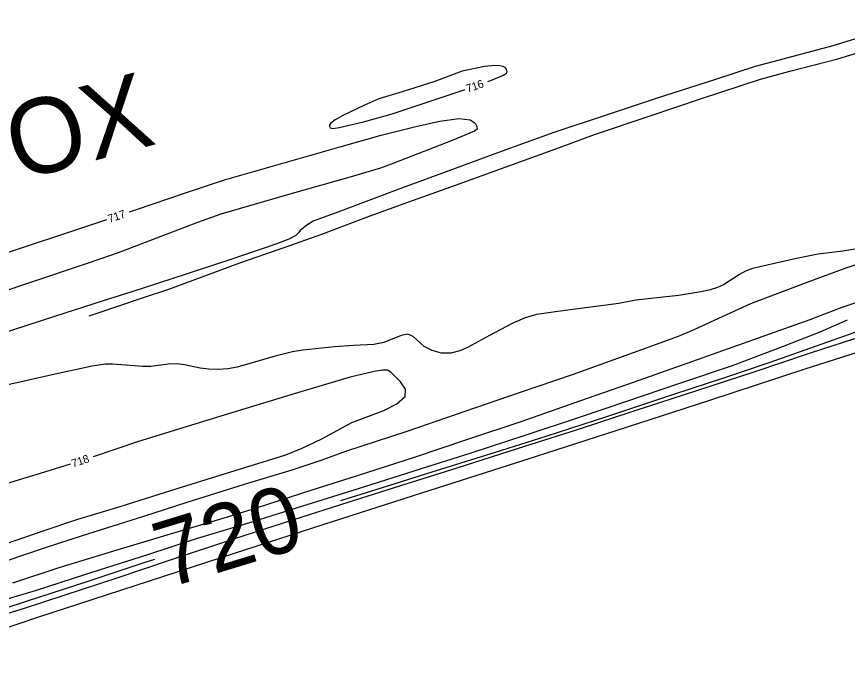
# Model space of a CAD drawing. Extents: x -361782338 to 28259792, y -263199453 to 8342113.
# Drawn here: x 1404244.3 to 1404659.4, y 576533.7 to 576861.6 of the extents above; entities that cross this region are included whole.
import ezdxf

# ---------------------------------------------------------------- set-up
doc = ezdxf.new("R2010")
doc.units = 0
for name, color, linetype in [('DT_X_Contour_Minor', 7, 'Continuous'), ('Level 14', 7, 'Continuous'), ('Level 19', 7, 'Continuous'), ('Level 40', 7, 'Continuous')]:
    doc.layers.add(name, color=color, linetype=linetype)

msp = doc.modelspace()

# ---------------------------------------------------------------- linework, layer by layer
at = {"layer": 'DT_X_Contour_Minor'}
for points in [[(1404699.46, 576861.58), (1404682.89, 576856.44), (1404652.1, 576846.96), (1404643.88, 576844.78)], [(1404280.47, 576711.95), (1404285.06, 576713.53), (1404307.26, 576720.99), (1404320.36, 576725.27), (1404337.02, 576731.47), (1404355.85, 576738.56), (1404378.05, 576746.14), (1404396.8, 576752.78), (1404421.02, 576762.02), (1404440.28, 576769.04), (1404463.56, 576777.37), (1404488.43, 576786.24), (1404515.51, 576796.09), (1404533.09, 576802.63), (1404560.28, 576811.8), (1404586.55, 576820.64), (1404616.02, 576830.31), (1404630.66, 576834.29), (1404654.64, 576840.5), (1404666.62, 576844.09)], [(1404643.88, 576844.78), (1404627.84, 576840.51), (1404613.37, 576836.57), (1404593.46, 576830.22), (1404563.83, 576820.63), (1404538.86, 576812.39), (1404512.65, 576803.66), (1404485.09, 576793.72), (1404460.32, 576784.56), (1404437.13, 576775.99), (1404404.79, 576763.83), (1404392.38, 576759.34), (1404389.33, 576757.38), (1404386.78, 576755.27)], [(1404479.73, 576829.1), (1404481.58, 576829.73), (1404487.62, 576832.33), (1404489.05, 576833.24), (1404489.47, 576833.93), (1404489.08, 576835.29), (1404488.52, 576836.02), (1404487.42, 576836.63), (1404485.63, 576837.02), (1404483.31, 576837.15), (1404478.11, 576836.65), (1404466.83, 576834.29), (1404452.71, 576828.93), (1404436.85, 576823.9), (1404425.34, 576820.48), (1404417.73, 576817.12), (1404407.66, 576812.26), (1404403.45, 576809.96), (1404401.22, 576808.34), (1404400.54, 576807.3), (1404400.63, 576806.56), (1404401, 576805.95), (1404402.29, 576805.71), (1404405.44, 576806.12), (1404417.58, 576809.05), (1404431.93, 576812.99), (1404457.98, 576821.63), (1404468.38, 576825.2)], [(1404300.71, 576763.93), (1404304.26, 576765.13), (1404328.6, 576773.47), (1404348.1, 576779.96), (1404372.67, 576786.91), (1404405.27, 576796.28), (1404426.48, 576802.3), (1404444.42, 576806.82), (1404455.73, 576809.28), (1404465.23, 576810.57), (1404470.88, 576810.04), (1404473.42, 576808.36), (1404474.25, 576806.56), (1404474.37, 576805.37), (1404473.04, 576804.3), (1404461.86, 576799.62), (1404432.8, 576788.24), (1404426.11, 576785.89), (1404411.46, 576781.54), (1404382.01, 576773.1), (1404360.58, 576766.96), (1404346.29, 576762.75), (1404334.62, 576758.71), (1404308.49, 576748.6), (1404295.08, 576743.5), (1404280.03, 576738.32), (1404249.74, 576728.19), (1404225.37, 576720.01)], [(1404217.54, 576736.11), (1404244.66, 576745.26), (1404273.34, 576754.75), (1404289.33, 576760.12)], [(1404386.78, 576755.27), (1404386, 576754.63), (1404385.14, 576753.44), (1404383.72, 576752.15), (1404380.27, 576750.39), (1404373.83, 576747.9), (1404350.79, 576740.07), (1404343.7, 576737.72)], [(1404667.17, 576745.99), (1404657.19, 576744.36), (1404644.72, 576742.83), (1404633.94, 576740.64), (1404611.97, 576735.63), (1404608.49, 576734.4), (1404605.44, 576732.73), (1404597.44, 576727.44), (1404594.48, 576726.16), (1404590.83, 576725.03), (1404586.21, 576723.96), (1404575.01, 576722.16), (1404553.7, 576719.77), (1404545.12, 576718.24), (1404518.39, 576714.58), (1404504.07, 576712.64), (1404498.41, 576710.97), (1404491.94, 576708.16), (1404480.49, 576702.08), (1404469.59, 576696.18), (1404465.76, 576694.45), (1404461.3, 576693.34), (1404456.55, 576693.41), (1404451.96, 576694.6), (1404448, 576696.69), (1404442.43, 576701.72), (1404439.74, 576702.89), (1404436.4, 576702.24), (1404427.82, 576698.69), (1404422.84, 576697.67), (1404412.61, 576697.13), (1404403.12, 576696.55), (1404387.34, 576694.84), (1404382.09, 576694), (1404373.4, 576691.9), (1404354.53, 576686.4), (1404349.84, 576685.57), (1404345.02, 576685.18), (1404340.31, 576685.25), (1404335.92, 576685.77), (1404328.2, 576687.54), (1404324.32, 576688), (1404320.08, 576687.77), (1404311.36, 576686.68), (1404307.35, 576686.66), (1404292.25, 576687.87), (1404288.66, 576687.78), (1404282.02, 576686.9), (1404265.11, 576683.16), (1404236.15, 576676.75)], [(1404229.05, 576586.24), (1404258.24, 576595.98), (1404277.28, 576602.26), (1404307.8, 576611.84), (1404329.5, 576618.8), (1404358.23, 576627.91), (1404381.97, 576635.09), (1404396.93, 576640.08), (1404408.71, 576644.35), (1404439.4, 576654.26), (1404468.42, 576664.34), (1404495.49, 576673.67), (1404522.49, 576682.9), (1404552.47, 576693.65), (1404575.02, 576701.9), (1404582.81, 576705.12), (1404611.08, 576718.22), (1404639.74, 576729.02), (1404658.21, 576735.81), (1404681.04, 576743.37)], [(1404343.7, 576737.72), (1404328.98, 576732.82), (1404301.91, 576724.01), (1404287.5, 576719.5), (1404263.17, 576711.61), (1404235.45, 576702.71), (1404203.09, 576692.14), (1404177.51, 576683.51), (1404146.48, 576673.07), (1404119.69, 576664.09), (1404091.39, 576655.12), (1404088.86, 576654.3)], [(1404684.97, 576725.7), (1404656.65, 576716.17), (1404645.77, 576711.99), (1404640.56, 576709.92), (1404614.86, 576700.76), (1404582.05, 576689.13), (1404552.35, 576678.7), (1404526.1, 576669.51), (1404496.16, 576659.07), (1404469.61, 576650.1), (1404442.87, 576641.21), (1404414.48, 576631.99), (1404391.87, 576624.77), (1404363.96, 576615.82), (1404347.25, 576610.67), (1404319.39, 576602.35), (1404294.42, 576594.78), (1404265.37, 576586.02), (1404242.23, 576578.4)], [(1404659.32, 576709.75), (1404645.64, 576703.9), (1404627.3, 576696.66), (1404601.77, 576687.08), (1404575.48, 576678.15), (1404548.46, 576668.96), (1404525.94, 576661.35), (1404498.21, 576652.2), (1404471.67, 576643.53), (1404442.68, 576634.33), (1404414.46, 576625.36), (1404387.09, 576616.82), (1404362.33, 576609.06), (1404334.07, 576600.47), (1404309.14, 576592.37), (1404278.65, 576582.61), (1404253.63, 576574.49), (1404226.33, 576566.45)], [(1404406.3, 576619.67), (1404421.85, 576624.55), (1404451.93, 576633.95), (1404483.54, 576643.77), (1404508.91, 576651.84), (1404539.63, 576661.86), (1404572.19, 576672.66), (1404599.22, 576681.48), (1404621.25, 576689.08), (1404651.93, 576699.89), (1404674.66, 576707.8)], [(1404218.66, 576556.83), (1404248.17, 576565.9), (1404268.08, 576572.35), (1404295.58, 576581.42), (1404321.7, 576590.23), (1404353.32, 576600.65), (1404382.78, 576610.16), (1404409.94, 576618.82), (1404439.39, 576628.26), (1404464.43, 576636.06), (1404494.58, 576645.67), (1404524.48, 576655.24), (1404553.83, 576664.87), (1404583.6, 576674.58), (1404613.23, 576684.22), (1404641.03, 576693.45), (1404668.73, 576702.56)], [(1404234.28, 576596.46), (1404258, 576604.67), (1404274.4, 576610.2), (1404295.94, 576616.66), (1404324.58, 576625.6), (1404353.41, 576634.71), (1404378.83, 576642.57), (1404386.89, 576645.78), (1404396.85, 576650.51), (1404411.77, 576658.71), (1404427.71, 576664.66), (1404434.28, 576667.92), (1404438.41, 576671.59), (1404438.58, 576675.4), (1404436.15, 576678.98), (1404431.2, 576683.86), (1404429.55, 576684.83), (1404427.04, 576684.9), (1404422.92, 576684.2), (1404410.9, 576681.36), (1404384.61, 576673.55), (1404358.3, 576665.44), (1404331.61, 576657.28), (1404304.73, 576649.02), (1404282.5, 576641.59)], [(1404271.08, 576637.9), (1404258.2, 576633.89), (1404227.89, 576624.76)], [(1404365.95, 576607.1), (1404366.3, 576607.2)], [(1404227.72, 576562.44), (1404249.17, 576569.31), (1404280.45, 576579.44), (1404308.48, 576588.77), (1404313.3, 576590.37)]]:
    msp.add_lwpolyline(points, dxfattribs=at)
at = {"layer": 'Level 14'}
msp.add_lwpolyline([(1404683.02, 576699.67), (1404638.14, 576685.26), (1404590.07, 576669.58), (1404543.76, 576654.5), (1404494.13, 576638.59), (1404446.54, 576623.29), (1404397.76, 576607.63), (1404352.95, 576593.18), (1404303.34, 576577.07), (1404254.75, 576561.14), (1404211.28, 576546.5), (1404172.05, 576533.75)], dxfattribs=at)

# ---------------------------------------------------------------- texts
at = {"layer": 'Level 19'}
for s, height, rotation, p in [('716', 4, 18.9592, (1404469.65, 576823.52)), ('717', 4, 18.5581, (1404290.67, 576758.46)), ('718', 4, 18.4779, (1404272.47, 576636.13)), ('720', 33, 16.9481, (1404319.27, 576575.62))]:
    msp.add_text(s, height=height, rotation=rotation, dxfattribs=at).set_placement(p)
at = {"layer": 'Level 40'}
msp.add_text("10'X5' BOX", height=37.5, rotation=15, dxfattribs=at).set_placement((1404067.53, 576731.75))

doc.saveas('drawing.dxf')
